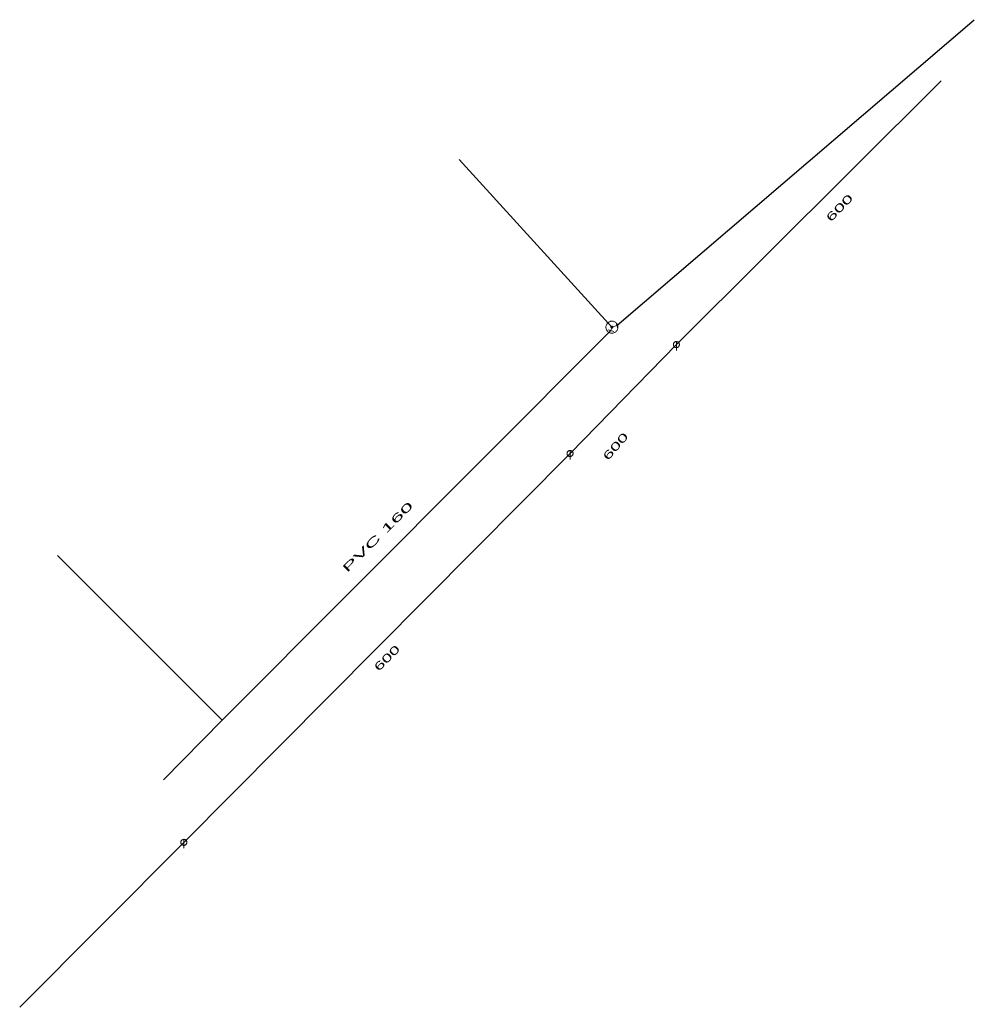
# Model space of a CAD drawing. Extents: x -687515 to -686506, y -974029 to -973461.
# Drawn here: x -687486.9 to -687407.3, y -973547.6 to -973465.4 of the extents above; entities that cross this region are included whole.
import ezdxf
from ezdxf.enums import TextEntityAlignment as Align

# ---------------------------------------------------------------- set-up
doc = ezdxf.new("R2010")
doc.units = 0
doc.header["$LTSCALE"] = 0.27
for name, color, linetype, lineweight in [('1', 7, 'Continuous', 13), ('13', 7, 'Continuous', 13), ('14', 7, 'Continuous', 25), ('17', 7, 'Continuous', 25), ('22', 7, 'Continuous', 13), ('34', 7, 'Continuous', 13), ('47', 7, 'Continuous', 13)]:
    doc.layers.add(name, color=color, linetype=linetype, lineweight=lineweight)

msp = doc.modelspace()

# ---------------------------------------------------------------- linework, layer by layer
at = {"layer": '13'}
for p, q in [((-687437.519, -973490.989), (-687450.249, -973477.02)), ((-687469.989, -973523.719), (-687483.709, -973509.999))]:
    msp.add_line(p, q, dxfattribs=at)
at = {"layer": '14', "lineweight": 13}
for q in [(-687437.608, -973491.274), (-687437.1, -973490.849)]:
    msp.add_line((-687437.519, -973490.989), q, dxfattribs=at)
at = {"layer": '14'}
msp.add_lwpolyline([(-687486.867, -973547.645), (-687473.19, -973533.907), (-687441.008, -973501.512), (-687432.147, -973492.439), (-687410.073, -973470.453)], dxfattribs=at)
at = {"layer": '17'}
msp.add_line((-687437.1, -973490.849), (-687407.323, -973465.375), dxfattribs=at)
msp.add_lwpolyline([(-687437.608, -973491.274), (-687469.989, -973523.719), (-687474.879, -973528.689)], dxfattribs=at)
at = {"layer": '22'}
for p, q in [((-687432.146, -973492.187), (-687432.147, -973492.931)), ((-687441.007, -973501.26), (-687441.008, -973502.004)), ((-687473.189, -973533.655), (-687473.19, -973534.399))]:
    msp.add_line(p, q, dxfattribs=at)
for points in [[(-687431.895, -973492.439), (-687431.896, -973492.413), (-687431.9, -973492.387), (-687431.906, -973492.361), (-687431.916, -973492.337), (-687431.928, -973492.313), (-687431.942, -973492.291), (-687431.959, -973492.27), (-687431.977, -973492.252), (-687431.998, -973492.235), (-687432.02, -973492.221), (-687432.044, -973492.209), (-687432.068, -973492.199), (-687432.094, -973492.193), (-687432.12, -973492.189), (-687432.146, -973492.187), (-687432.172, -973492.188), (-687432.198, -973492.192), (-687432.224, -973492.198), (-687432.249, -973492.208), (-687432.272, -973492.22), (-687432.294, -973492.234), (-687432.315, -973492.251), (-687432.333, -973492.269), (-687432.35, -973492.29), (-687432.364, -973492.312), (-687432.376, -973492.336), (-687432.386, -973492.36), (-687432.393, -973492.386), (-687432.397, -973492.412), (-687432.399, -973492.438), (-687432.398, -973492.464), (-687432.394, -973492.49), (-687432.387, -973492.516), (-687432.377, -973492.541), (-687432.365, -973492.564), (-687432.351, -973492.586), (-687432.334, -973492.607), (-687432.316, -973492.625), (-687432.295, -973492.642), (-687432.273, -973492.656), (-687432.25, -973492.668), (-687432.225, -973492.678), (-687432.199, -973492.685), (-687432.173, -973492.689), (-687432.147, -973492.691), (-687432.121, -973492.69), (-687432.095, -973492.686), (-687432.069, -973492.679), (-687432.045, -973492.669), (-687432.021, -973492.657), (-687431.999, -973492.643), (-687431.978, -973492.626), (-687431.96, -973492.608), (-687431.943, -973492.587), (-687431.929, -973492.565), (-687431.917, -973492.542), (-687431.907, -973492.517), (-687431.901, -973492.491), (-687431.897, -973492.465)], [(-687440.756, -973501.512), (-687440.757, -973501.486), (-687440.761, -973501.46), (-687440.767, -973501.434), (-687440.777, -973501.41), (-687440.789, -973501.386), (-687440.803, -973501.364), (-687440.82, -973501.343), (-687440.838, -973501.325), (-687440.859, -973501.308), (-687440.881, -973501.294), (-687440.905, -973501.282), (-687440.929, -973501.272), (-687440.955, -973501.266), (-687440.981, -973501.262), (-687441.007, -973501.26), (-687441.033, -973501.261), (-687441.059, -973501.265), (-687441.085, -973501.271), (-687441.11, -973501.281), (-687441.133, -973501.293), (-687441.155, -973501.307), (-687441.176, -973501.324), (-687441.194, -973501.342), (-687441.211, -973501.363), (-687441.225, -973501.385), (-687441.237, -973501.409), (-687441.247, -973501.433), (-687441.254, -973501.459), (-687441.258, -973501.485), (-687441.26, -973501.511), (-687441.259, -973501.537), (-687441.255, -973501.563), (-687441.248, -973501.589), (-687441.238, -973501.614), (-687441.226, -973501.637), (-687441.212, -973501.659), (-687441.195, -973501.68), (-687441.177, -973501.698), (-687441.156, -973501.715), (-687441.134, -973501.729), (-687441.111, -973501.741), (-687441.086, -973501.751), (-687441.06, -973501.758), (-687441.034, -973501.762), (-687441.008, -973501.764), (-687440.982, -973501.763), (-687440.956, -973501.759), (-687440.93, -973501.752), (-687440.906, -973501.742), (-687440.882, -973501.73), (-687440.86, -973501.716), (-687440.839, -973501.699), (-687440.821, -973501.681), (-687440.804, -973501.66), (-687440.79, -973501.638), (-687440.778, -973501.615), (-687440.768, -973501.59), (-687440.762, -973501.564), (-687440.758, -973501.538)], [(-687472.938, -973533.907), (-687472.939, -973533.881), (-687472.943, -973533.855), (-687472.949, -973533.829), (-687472.959, -973533.805), (-687472.971, -973533.781), (-687472.985, -973533.759), (-687473.002, -973533.738), (-687473.02, -973533.72), (-687473.041, -973533.703), (-687473.063, -973533.689), (-687473.087, -973533.677), (-687473.111, -973533.667), (-687473.137, -973533.661), (-687473.163, -973533.657), (-687473.189, -973533.655), (-687473.215, -973533.656), (-687473.241, -973533.66), (-687473.267, -973533.666), (-687473.292, -973533.676), (-687473.315, -973533.688), (-687473.337, -973533.702), (-687473.358, -973533.719), (-687473.376, -973533.737), (-687473.393, -973533.758), (-687473.407, -973533.78), (-687473.419, -973533.804), (-687473.429, -973533.828), (-687473.436, -973533.854), (-687473.44, -973533.88), (-687473.441, -973533.906), (-687473.441, -973533.932), (-687473.437, -973533.958), (-687473.43, -973533.984), (-687473.42, -973534.009), (-687473.408, -973534.032), (-687473.394, -973534.054), (-687473.377, -973534.075), (-687473.359, -973534.093), (-687473.338, -973534.11), (-687473.316, -973534.124), (-687473.293, -973534.136), (-687473.268, -973534.146), (-687473.242, -973534.153), (-687473.216, -973534.157), (-687473.19, -973534.159), (-687473.164, -973534.158), (-687473.138, -973534.154), (-687473.112, -973534.147), (-687473.088, -973534.137), (-687473.064, -973534.125), (-687473.042, -973534.111), (-687473.021, -973534.094), (-687473.003, -973534.076), (-687472.986, -973534.055), (-687472.972, -973534.033), (-687472.96, -973534.01), (-687472.95, -973533.985), (-687472.944, -973533.959), (-687472.94, -973533.933)]]:
    msp.add_lwpolyline(points, close=True, dxfattribs=at)
at = {"layer": '34'}
for p, q in [((-687437.021, -973491.084), (-687437.178, -973490.613)), ((-687437.371, -973491.347), (-687437.844, -973491.2))]:
    msp.add_line(p, q, dxfattribs=at)
at = {"layer": '47'}
for points in [[(-687437.182, -973491.358), (-687437.145, -973491.321), (-687437.112, -973491.28), (-687437.085, -973491.236), (-687437.061, -973491.19), (-687437.042, -973491.14), (-687437.029, -973491.089), (-687437.022, -973491.038), (-687437.019, -973490.985), (-687437.022, -973490.934), (-687437.03, -973490.882), (-687437.044, -973490.831), (-687437.064, -973490.782), (-687437.087, -973490.736), (-687437.116, -973490.692), (-687437.149, -973490.652), (-687437.186, -973490.615), (-687437.227, -973490.582), (-687437.272, -973490.554), (-687437.317, -973490.531), (-687437.367, -973490.512), (-687437.418, -973490.499), (-687437.47, -973490.491), (-687437.522, -973490.489), (-687437.574, -973490.491), (-687437.625, -973490.5), (-687437.676, -973490.514), (-687437.725, -973490.533), (-687437.771, -973490.557), (-687437.815, -973490.586), (-687437.855, -973490.619), (-687437.892, -973490.656), (-687437.925, -973490.697), (-687437.954, -973490.741), (-687437.976, -973490.787), (-687437.995, -973490.837), (-687438.009, -973490.887), (-687438.017, -973490.939), (-687438.019, -973490.991), (-687438.016, -973491.044), (-687438.007, -973491.095), (-687437.993, -973491.146), (-687437.975, -973491.195), (-687437.95, -973491.241), (-687437.921, -973491.285), (-687437.888, -973491.325), (-687437.851, -973491.362), (-687437.81, -973491.395), (-687437.767, -973491.423), (-687437.72, -973491.446), (-687437.67, -973491.465), (-687437.62, -973491.479), (-687437.569, -973491.486), (-687437.516, -973491.488), (-687437.464, -973491.485), (-687437.412, -973491.477), (-687437.361, -973491.463), (-687437.313, -973491.444), (-687437.266, -973491.42), (-687437.222, -973491.391)], [(-687437.463, -973491.049), (-687437.457, -973491.043), (-687437.452, -973491.036), (-687437.447, -973491.029), (-687437.444, -973491.022), (-687437.44, -973491.013), (-687437.439, -973491.005), (-687437.437, -973490.997), (-687437.436, -973490.988), (-687437.437, -973490.98), (-687437.438, -973490.971), (-687437.441, -973490.962), (-687437.444, -973490.954), (-687437.448, -973490.947), (-687437.452, -973490.94), (-687437.458, -973490.933), (-687437.464, -973490.927), (-687437.471, -973490.922), (-687437.478, -973490.917), (-687437.485, -973490.914), (-687437.494, -973490.91), (-687437.502, -973490.909), (-687437.51, -973490.907), (-687437.519, -973490.906), (-687437.528, -973490.907), (-687437.536, -973490.908), (-687437.545, -973490.911), (-687437.553, -973490.914), (-687437.56, -973490.918), (-687437.567, -973490.922), (-687437.574, -973490.928), (-687437.58, -973490.934), (-687437.585, -973490.941), (-687437.59, -973490.948), (-687437.593, -973490.955), (-687437.597, -973490.964), (-687437.599, -973490.971), (-687437.6, -973490.98), (-687437.601, -973490.989), (-687437.6, -973490.998), (-687437.599, -973491.006), (-687437.596, -973491.015), (-687437.593, -973491.023), (-687437.589, -973491.03), (-687437.585, -973491.037), (-687437.579, -973491.044), (-687437.573, -973491.05), (-687437.566, -973491.055), (-687437.559, -973491.06), (-687437.552, -973491.063), (-687437.543, -973491.067), (-687437.536, -973491.069), (-687437.527, -973491.07), (-687437.518, -973491.071), (-687437.51, -973491.07), (-687437.501, -973491.069), (-687437.492, -973491.066), (-687437.484, -973491.063), (-687437.477, -973491.059), (-687437.47, -973491.055)]]:
    msp.add_lwpolyline(points, close=True, dxfattribs=at)

# ---------------------------------------------------------------- texts
at = {"layer": '1'}
for s, rotation, width, p in [('600 ', 46, 1.85, (-687418.156, -973481.11)), ('600 ', 49, 1.8, (-687436.821, -973500.966)), ('PVC 160 ', 45, 2.2, (-687456.609, -973508.506)), ('600 ', 45, 1.75, (-687455.876, -973518.633))]:
    msp.add_text(s, height=0.6667, rotation=rotation, dxfattribs=dict(at, width=width)).set_placement(p, align=Align.CENTER)

doc.saveas('drawing.dxf')
